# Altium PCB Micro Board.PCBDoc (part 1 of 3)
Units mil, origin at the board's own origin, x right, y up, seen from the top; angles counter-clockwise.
Board outline 8525 x 5525 mil, 2 copper layers (Top Layer, Bottom Layer); 82 components, 533 nets, 1257 pads, 165 vias.
Unrouted connection lines stored in the file: 4.
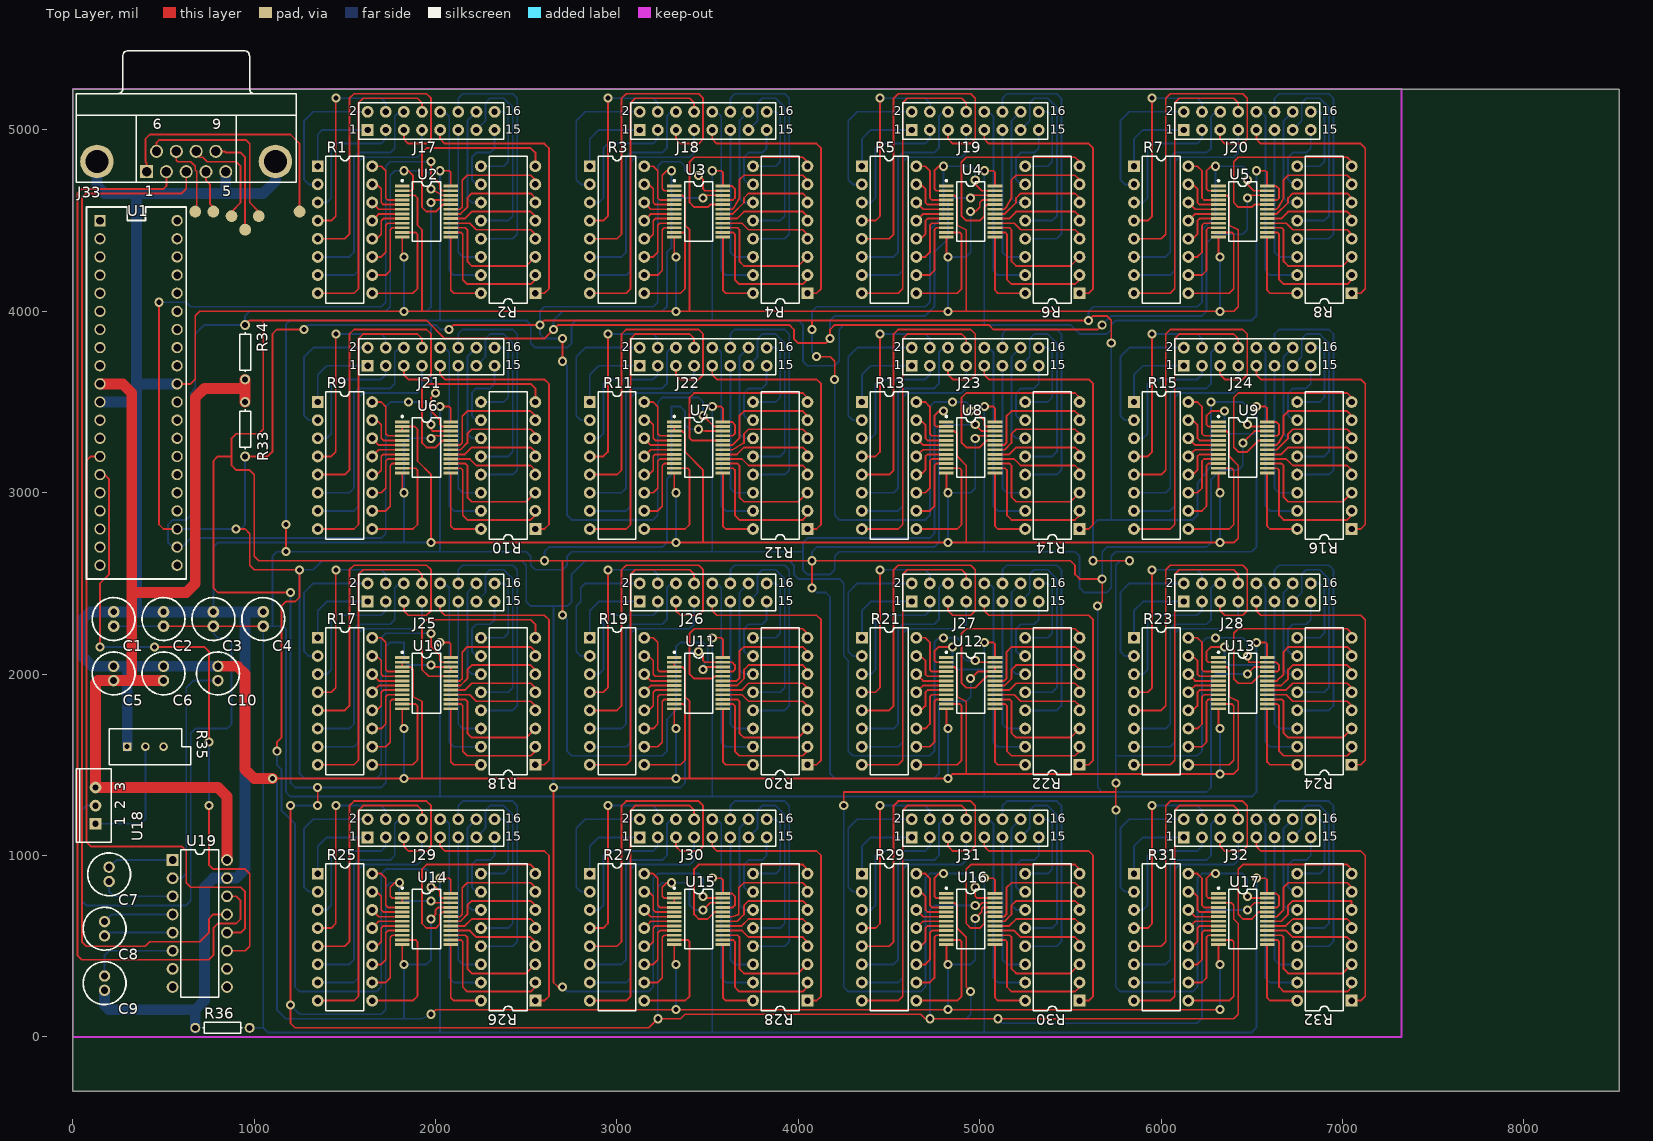
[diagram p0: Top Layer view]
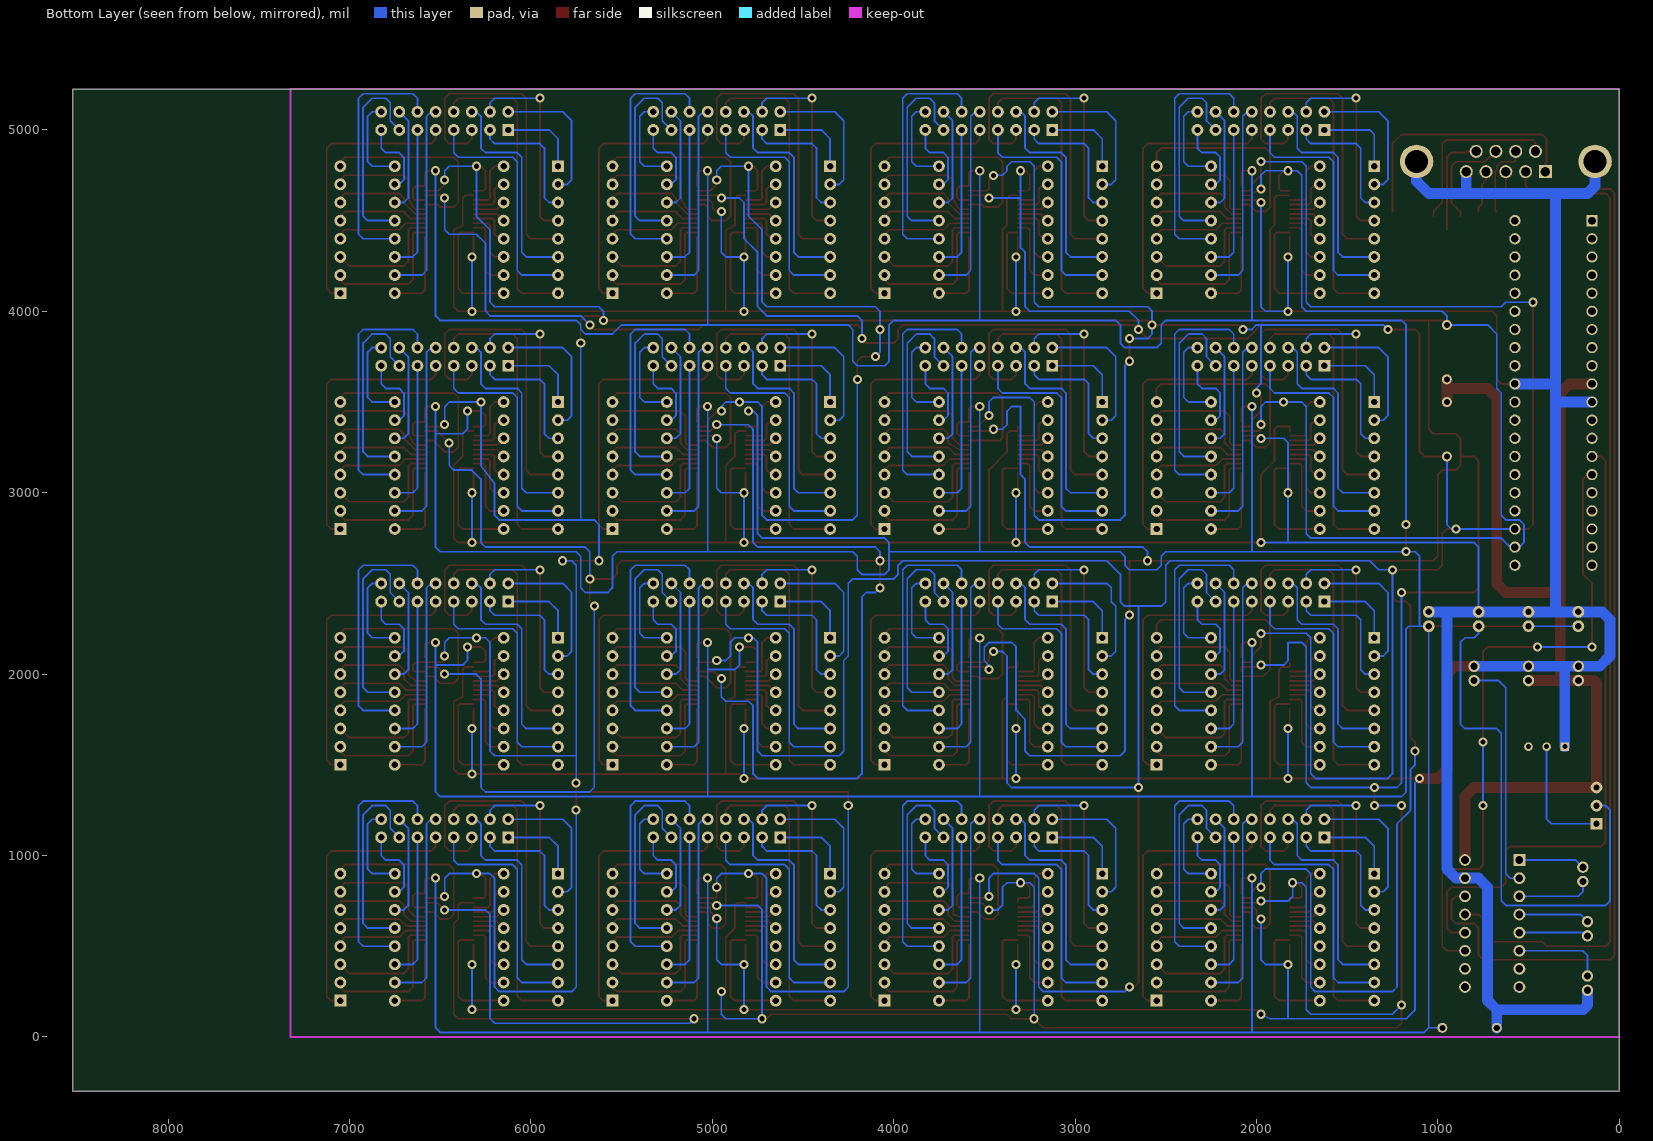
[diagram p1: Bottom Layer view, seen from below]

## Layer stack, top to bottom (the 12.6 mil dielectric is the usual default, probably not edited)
Top Layer: signal copper 1.4
Dielectric: dielectric 12.6, FR-4, Dk 4.8
Bottom Layer: signal copper 1.4

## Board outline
0,-300 8525,-300 8525,5225 0,5225

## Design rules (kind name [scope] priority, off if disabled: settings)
Clearance [All] p1: gap=9.84
ComponentClearance [All] p1: gap=10 collisioncheckmode=0
PolygonConnect [All] p1: connectstyle=Relief reliefconductorwidth=10 reliefentries=4 polygonreliefangle="90 Angle"
RoutingLayers [All] p1: top layer=Horizontal bottom layer=Vertical
RoutingVias [All] p1: holewidth=28 width=50 viastyle="Through Hole" minholewidth=28 minwidth=50 maxholewidth=28 maxwidth=50
SolderMaskExpansion [All] p1: expansion=4
TestPointUsage [All] p1: valid=0 allowmultiple=FALSE
Testpoint [All] p1: side=15 testpointundercomponent=TRUE minsize=40 maxsize=100 preferedsize=60 minholesize=0 maxholesize=40 preferedholesize=32 testpointgrid=1 style=1023 order=-539222988
Width [InNetClass('B[1..256]')] p1: maxlimit=10 minlimit=10 preferedwidth=10
16 further rules are at their usual default settings.

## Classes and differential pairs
component class "Drivers 1": C1 U2 U3 U4 U5
component class "Drivers 2": C2 U6 U7 U8 U9
component class "Drivers 3": C3 U10 U11 U12 U13
component class "Drivers 4": C4 U14 U15 U16 U17
component class Microprocessor: C5 C6 C7 C8 C9 C10 J33 R33 R34 R35 R36 U1 U18 U19
component class "Output Headers 1": J17 J18 J19 J20 J21 J22 J23 J24 J25 R1 R2 R3 R4 R5 R6 R7 R8 R9 R10 R11 R12 R13 R14 R15 R16 R17 R18
component class "Output Headers 2": J26 J27 J28 J29 J30 J31 J32 R19 R20 R21 R22 R23 R24 R25 R26 R27 R28 R29 R30 R31 R32
net class B[1..256]: B1 B2 B3 B4 B5 B6 B7 B8 B9 B10 B11 B12 B13 B14 B15 B16 B17 B18 B19 B20 B21 B22 B23 B24 B25 B26 B27 B28 B29 B30 B31 B32 B33 B34 B35 B36 B37 B38 B39 B40 B41 B42 B43 B44 B45 B46 B47 B48 B49 B50 B51 B52 B53 B54 B55 B56 B57 B58 B59 B60 B61 B62 B63 B64 B65 B66 B67 B68 B69 B70 B71 B72 B73 B74 B75 B76 B77 B78 B79 B80 B81 B82 B83 B84 B85 B86 B87 B88 B89 B90 B91 B92 B93 B94 B95 B96 B97 B98 B99 B100 B101 B102 B103 B104 B105 B106 B107 B108 B109 B110 B111 B112 B113 B114 B115 B116 B117 B118 B119 B120 B121 B122 B123 B124 B125 B126 B127 B128 B129 B130 B131 B132 B133 B134 B135 B136 B137 B138 B139 B140 B141 B142 B143 B144 B145 B146 B147 B148 B149 B150 B151 B152 B153 B154 B155 B156 B157 B158 B159 B160 B161 B162 B163 B164 B165 B166 B167 B168 B169 B170 B171 B172 B173 B174 B175 B176 B177 B178 B179 B180 B181 B182 B183 B184 B185 B186 B187 B188 B189 B190 B191 B192 B193 B194 B195 B196 B197 B198 B199 B200 B201 B202 B203 B204 B205 B206 B207 B208 B209 B210 B211 B212 B213 B214 B215 B216 B217 B218 B219 B220 B221 B222 B223 B224 B225 B226 B227 B228 B229 B230 B231 B232 B233 B234 B235 B236 B237 B238 B239 B240 B241 B242 B243 B244 B245 B246 B247 B248 B249 B250 B251 B252 B253 B254 B255 B256

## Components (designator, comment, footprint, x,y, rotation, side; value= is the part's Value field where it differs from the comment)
C1 "47nF" LED#1 225,2225 r0 top
C2 "47nF" LED#1 500,2225 r0 top
C3 "47nF" LED#1 775,2225 r0 top
C4 "47nF" LED#1 1050,2225 r0 top
C5 "0.1uF" LED#2 225,1925 r0 top
C6 "1uF" LED#2 500,1925 r0 top
C7 "1uF" LED#2 200,975 r180 top
C8 "1uF" LED#2 175,675 r180 top
C9 "1uF" LED#2 175,375 r180 top
C10 "1uF" LED#2 800,1925 r0 top
J17 "HDR2X8" HDR2X8 1625,5000 r0 top
J18 "HDR2X8" HDR2X8 3125,5000 r0 top
J19 "HDR2X8" HDR2X8 4625,5000 r0 top
J20 "HDR2X8" HDR2X8 6125,5000 r0 top
J21 "HDR2X8" HDR2X8 1625,3700 r0 top
J22 "HDR2X8" HDR2X8 3125,3700 r0 top
J23 "HDR2X8" HDR2X8 4625,3700 r0 top
J24 "HDR2X8" HDR2X8 6125,3700 r0 top
J25 "HDR2X8" HDR2X8 1625,2400 r0 top
J26 "HDR2X8" HDR2X8 3125,2400 r0 top
J27 "HDR2X8" HDR2X8 4625,2400 r0 top
J28 "HDR2X8" HDR2X8 6125,2400 r0 top
J29 "HDR2X8" HDR2X8 1625,1100 r0 top
J30 "HDR2X8" HDR2X8 3125,1100 r0 top
J31 "HDR2X8" HDR2X8 4625,1100 r0 top
J32 "HDR2X8" HDR2X8 6125,1100 r0 top
J33 "D Connector 9" DSUB1.385-2H9 625,5200 r0 top
R1 "330" DIP-16#1 1500,4450 r270 top
R2 "330" DIP-16#1 2400,4450 r90 top
R3 "330" DIP-16#1 3000,4450 r270 top
R4 "330" DIP-16#1 3900,4450 r90 top
R5 "330" DIP-16#1 4500,4450 r270 top
R6 "330" DIP-16#1 5400,4450 r90 top
R7 "330" DIP-16#1 6000,4450 r270 top
R8 "330" DIP-16#1 6900,4450 r90 top
R9 "330" DIP-16#1 1500,3150 r270 top
R10 "330" DIP-16#1 2400,3150 r90 top
R11 "330" DIP-16#1 3000,3150 r270 top
R12 "330" DIP-16#1 3900,3150 r90 top
R13 "330" DIP-16#1 4500,3150 r270 top
R14 "330" DIP-16#1 5400,3150 r90 top
R15 "330" DIP-16#1 6000,3150 r270 top
R16 "330" DIP-16#1 6900,3150 r90 top
R17 "330" DIP-16#1 1500,1850 r270 top
R18 "330" DIP-16#1 2400,1850 r90 top
R19 "330" DIP-16#1 3000,1850 r270 top
R20 "330" DIP-16#1 3900,1850 r90 top
R21 "330" DIP-16#1 4500,1850 r270 top
R22 "330" DIP-16#1 5400,1850 r90 top
R23 "330" DIP-16#1 6000,1850 r270 top
R24 "330" DIP-16#1 6900,1850 r90 top
R25 "330" DIP-16#1 1500,550 r270 top
R26 "330" DIP-16#1 2400,550 r90 top
R27 "330" DIP-16#1 3000,550 r270 top
R28 "330" DIP-16#1 3900,550 r90 top
R29 "330" DIP-16#1 4500,550 r270 top
R30 "330" DIP-16#1 5400,550 r90 top
R31 "330" DIP-16#1 6000,550 r270 top
R32 "330" DIP-16#1 6900,550 r90 top
R33 "1k8" AXIAL-0.3 950,3350 r90 top
R34 "1k8" AXIAL-0.3 950,3775 r270 top
R35 "1k" VR5 400,1600 r0 top
R36 "330" AXIAL-0.3 825,50 r0 top
U1 "ATMEGA16" DIP-40 75,2525 r0 top
U2 "MAX7313" SSO-G24/C6.8 1950,4550 r270 top
U3 "MAX7313" SSO-G24/C6.8 3450,4550 r270 top
U4 "MAX7313" SSO-G24/C6.8 4950,4550 r270 top
U5 "MAX7313" SSO-G24/C6.8 6450,4550 r270 top
U6 "MAX7313" SSO-G24/C6.8 1950,3250 r270 top
U7 "MAX7313" SSO-G24/C6.8 3450,3250 r270 top
U8 "MAX7313" SSO-G24/C6.8 4950,3250 r270 top
U9 "MAX7313" SSO-G24/C6.8 6450,3250 r270 top
U10 "MAX7313" SSO-G24/C6.8 1950,1950 r270 top
U11 "MAX7313" SSO-G24/C6.8 3450,1950 r270 top
U12 "MAX7313" SSO-G24/C6.8 4950,1950 r270 top
U13 "MAX7313" SSO-G24/C6.8 6450,1950 r270 top
U14 "MAX7313" SSO-G24/C6.8 1950,650 r270 top
U15 "MAX7313" SSO-G24/C6.8 3450,650 r270 top
U16 "MAX7313" SSO-G24/C6.8 4950,650 r270 top
U17 "MAX7313" SSO-G24/C6.8 6450,650 r270 top
U18 "LM317BT" SFM-T3/X1.6V 125,1275 r90 top
U19 "MAX232E" DIP-16#2 700,625 r270 top

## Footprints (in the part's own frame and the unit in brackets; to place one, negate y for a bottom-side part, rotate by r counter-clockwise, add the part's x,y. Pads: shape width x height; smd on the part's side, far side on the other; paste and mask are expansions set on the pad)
AXIAL-0.3 [mm]
  round 1.4 hole 0.85: 1(-3.81,0) 2(3.81,0)
  silkscreen extent -2.77,-0.76 2.77,0.76
DIP-16#1 [mil]
  rect 65x65 hole 35: 1(-350,-150)
  round 65 hole 35: 2(-250,-150) 3(-150,-150) 4(-50,-150) 5(50,-150) 6(150,-150) 7(250,-150) 8(350,-150) 9(350,150) 10(250,150) 11(150,150) 12(50,150) 13(-50,150) 14(-150,150) 15(-250,150) 16(-350,150)
  silkscreen extent -406,-104 406,104
DIP-16#2 [mil]
  rect 65x65 hole 42: 1(-350,-150)
  round 65 hole 42: 2(-250,-150) 3(-150,-150) 4(-50,-150) 5(50,-150) 6(150,-150) 7(250,-150) 8(350,-150) 9(350,150) 10(250,150) 11(150,150) 12(50,150) 13(-50,150) 14(-150,150) 15(-250,150) 16(-350,150)
  silkscreen extent -406,-104 406,104
DIP-40 [mil]
  rect 62x62 hole 42: 1(75,1975)
  round 62 hole 42: 2(75,1875) 3(75,1775) 4(75,1675) 5(75,1575) 6(75,1475) 7(75,1375) 8(75,1275) 9(75,1175) 10(75,1075) 11(75,975) 12(75,875) 13(75,775) 14(75,675) 15(75,575) 16(75,475) 17(75,375) 18(75,275) 19(75,175) 20(75,75) 21(500,75) 22(500,175) 23(500,275) 24(500,375) 25(500,475) 26(500,575) 27(500,675) 28(500,775) 29(500,875) 30(500,975) 31(500,1075) 32(500,1175) 33(500,1275) 34(500,1375) 35(500,1475) 36(500,1575) 37(500,1675) 38(500,1775) 39(500,1875) 40(500,1975)
  silkscreen extent 0,0 550,2050
DSUB1.385-2H9 [mil]
  rect 72x72 hole 52: 1(-218.11,-429.92)
  round 72 hole 52: 2(-109.06,-429.92) 3(0,-429.92) 4(109.06,-429.92) 5(218.11,-429.92) 6(-163.58,-318.11) 7(-54.53,-318.11) 8(54.53,-318.11) 9(163.58,-318.11)
  round 185 hole 125: 10(-491.93,-374.02) 11(491.93,-374.02)
  silkscreen extent -606,-488 606,236
HDR2X8 [mil]
  rect 65x65 hole 35: 1(0,0)
  round 65 hole 35: 2(0,100) 3(100,0) 4(100,100) 5(200,0) 6(200,100) 7(300,0) 8(300,100) 9(400,0) 10(400,100) 11(500,0) 12(500,100) 13(600,0) 14(600,100) 15(700,0) 16(700,100)
  silkscreen extent -50,-50 750,150
LED#1 [mil]
  round 65 hole 35: 1(0,39.37) 2(0,118.11)
  silkscreen extent -118,-39 118,197
LED#2 [mil]
  round 62.99 hole 39.37: 1(0,39.37) 2(0,118.11)
  silkscreen extent -118,-39 118,197
SFM-T3/X1.6V [mil]
  rect 65x65 hole 35: 1(-100,0)
  round 65 hole 35: 2(0,0) 3(100,0)
  silkscreen extent -203,-87 203,106
SSO-G24/C6.8 [mm]
  rect 0.4x2.05 smd: 1(-3.575,-3.4) 2(-2.925,-3.4) 3(-2.275,-3.4) 4(-1.625,-3.4) 5(-0.975,-3.4) 6(-0.325,-3.4) 7(0.325,-3.4) 8(0.975,-3.4) 9(1.625,-3.4) 10(2.275,-3.4) 11(2.925,-3.4) 12(3.575,-3.4) 13(3.575,3.4) 14(2.925,3.4) 15(2.275,3.4) 16(1.625,3.4) 17(0.975,3.4) 18(0.325,3.4) 19(-0.325,3.4) 20(-0.975,3.4) 21(-1.625,3.4) 22(-2.275,3.4) 23(-2.925,3.4) 24(-3.575,3.4)
  silkscreen extent -4.45,-3.52 4.18,1.98
VR5 [mm]
  rect 1.2x1.2 hole 0.7: 1(-2.54,0)
  round 1.2 hole 0.7: 2(0,0) 3(2.54,0)
  silkscreen extent -5.08,-2.54 6.35,2.54

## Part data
C1 C2 C3 C4 C5 C6 C7 C8 C9 C10: library part Cap, "Capacitor"
J17 J18 J19 J20 J21 J22 J23 J24 J25 J26 J27 J28 J29 J30 J31 J32: library part MHDR1X16, "Header, 16-Pin"
J33: "Receptacle Assembly, 9 Position, Right Angle"
R1 R2 R3 R4 R5 R6 R7 R8 R9 R10 R11 R12 R13 R14 R15 R16 R17 R18 R19 R20 R21 R22 R23 R24 R25 R26 R27 R28 R29 R30 R31 R32: library part "Res Pack2", "Resistor Array - Parts"
R33 R34 R36: library part Res1, "Resistor"
R35: library part RPot1, "Potentiometer"
U2 U3 U4 U5 U6 U7 U8 U9 U10 U11 U12 U13 U14 U15 U16 U17: library part "LED DRIVER"
U18: "3-Terminal Adjustable Positive Voltage Regulator"
U19: library part MAX232N, "Dual EIA-232 Driver/Receiver"

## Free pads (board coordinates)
  round 65 smd: 1(675,4550) 2(775,4550) 3(1250,4550) 4(875,4525) 5(950,4450) 6(1025,4525)

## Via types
v1: diameter 50, hole 28, Top Layer to Bottom Layer, 165 vias

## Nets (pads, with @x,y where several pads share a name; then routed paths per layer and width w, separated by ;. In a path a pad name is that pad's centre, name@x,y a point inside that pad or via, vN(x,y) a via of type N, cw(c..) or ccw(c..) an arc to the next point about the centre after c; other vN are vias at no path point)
+5: C5.1 C6.1 R33.2 R34.2 U1.10 U18.3 U19.16 | length 5664.5
  Top Layer w10: C5.1@214.37,1975 C5.1@225,1964.37
  Top Layer w60: U1.10@150,3600 275,3600 325,3550 325,1964.37 ; 325,2450 625,2450 675,2500 675,3525 725,3575 950,3575 ; C6.1@500,1964.37 139.37,1964.37 125,1950 U18.3@125,1375 800,1375 850,1325 U19.16@850,975 ; R33.2@950,3500 R34.2@950,3625
B1: R1.1 R1.16 U2.4 | length 331.1
  Top Layer w10: R1.16@1650,4800 1700,4800 1725,4775 1725,4625 1736.02,4613.98 U2.4@1816.14,4613.98
B1: J17.1 | length 460.4
  Bottom Layer w10: 1350,4800 1350,4950 1350,4975 1375,5000 J17.1@1625,5000
B2: R1.2 R1.15 U2.5 | length 256.3
  Top Layer w10: R1.15@1650,4700 1675,4700 1700,4675 1700,4600 1711.61,4588.39 U2.5@1816.14,4588.39
B2: J17.2 | length 781.1
  Bottom Layer w10: 1350,4700 1300,4700 1275,4725 1275,5050 1325,5100 J17.2@1625,5100
B3: R1.14 U2.6 | length 181.6
  Top Layer w10: R1.14@1650,4600 1687.2,4562.8 U2.6@1816.14,4562.8
B3: J17.3 R1.3 | length 731.1
  Bottom Layer w10: R1.3@1350,4600 1400,4600 1425,4625 1425,4900 1450,4925 1700,4925 1725,4950 J17.3@1725,5000
B4: R1.13 U2.7 | length 146.2
  Top Layer w10: 1675,4525 1687.2,4537.2 U2.7@1816.14,4537.2
B4: J17.4 R1.4 | length 1095.7
  Top Layer w10: R1.4@1350,4500 1425,4500 1450,4525 v1(1450,5175)
  Bottom Layer w10: v1(1450,5175) 1700,5175 1725,5150 J17.4@1725,5100
B5: R1.12 U2.8 | length 256.3
  Top Layer w10: R1.12@1650,4400 1675,4400 1700,4425 1700,4500 1711.61,4511.61 U2.8@1816.14,4511.61
B5: J17.5 R1.5 | length 1851.8
  Top Layer w10: R1.5@1350,4400 1500,4400 1525,4425 1525,5175 1550,5200 1950,5200 1975,5175 1975,4950 1950,4925 1850,4925 1825,4950 J17.5@1825,5000
B6: R1.11 U2.9 | length 331.1
  Top Layer w10: R1.11@1650,4300 1700,4300 1725,4325 1725,4475 1736.02,4486.02 U2.9@1816.14,4486.02
B6: J17.6 R1.6 | length 1216.4
  Bottom Layer w10: R1.6@1350,4300 1525,4300 1550,4325 1550,4850 1575,4875 1750,4875 1775,4900 1775,5075 1800,5100 J17.6@1825,5100
B7: R1.10 U2.10 | length 405.8
  Top Layer w10: R1.10@1650,4200 1725,4200 1750,4225 1750,4450 1760.43,4460.43 U2.10@1816.14,4460.43
B7: J17.7 R1.7 | length 1331.1
  Bottom Layer w10: R1.7@1350,4200 1550,4200 1575,4225 1575,4825 1600,4850 1900,4850 1925,4875 J17.7@1925,5000
B8: R1.9 U2.11 | length 648.3
  Top Layer w10: R1.9@1650,4100 1875,4100 1900,4125 1900,4425 1890.16,4434.84 U2.11@1816.14,4434.84
B8: J17.8 R1.8 | length 1681.1
  Top Layer w10: R1.8@1350,4100 1550,4100 1575,4125 1575,5150 1600,5175 1900,5175 1925,5150 J17.8@1925,5100
B9: R2.1 R2.16 U2.13 | length 465.9
  Top Layer w10: U2.13@2083.86,4409.25 2083.86,4116.14 2100,4100 R2.16@2250,4100
B9: J17.9 | length 1531.1
  Top Layer w10: J17.9@2025,5000 2025,4950 2050,4925 2600,4925 2625,4900 2625,4125 2600,4100 2550,4100
B10: J17.10 R2.15 | length 1095.7
  Bottom Layer w10: J17.10@2025,5100 2050,5100 2075,5075 2075,4225 2100,4200 R2.15@2250,4200
B10: R2.2 U2.14 | length 765.9
  Top Layer w10: U2.14@2083.86,4434.84 2140.16,4434.84 2150,4425 2150,4175 2175,4150 2525,4150 2550,4175 R2.2@2550,4200
B11: J17.11 R2.3 R2.14 | length 810.4
  Bottom Layer w10: J17.11@2125,5000 2125,4325 2150,4300 R2.14@2250,4300
B11: U2.15 | length 676.5
  Top Layer w10: U2.15@2083.86,4460.43 2164.57,4460.43 2175,4450 2175,4275 2200,4250 2500,4250 2550,4300
B12: J17.12 R2.13 | length 1381.1
  Bottom Layer w10: J17.12@2125,5100 2125,5175 2150,5200 2425,5200 2450,5175 2450,4425 2425,4400 R2.13@2250,4400
B12: R2.4 U2.16 | length 516.4
  Top Layer w10: U2.16@2083.86,4486.02 2188.98,4486.02 2225,4450 2525,4450 2550,4425 R2.4@2550,4400
B13: J17.13 R2.12 | length 1137.1
  Bottom Layer w10: J17.13@2225,5000 2275,5050 2275,5150 2300,5175 2375,5175 2425,5125 2425,4525 2400,4500 R2.12@2250,4500
B13: R2.5 U2.17 | length 517.4
  Top Layer w10: U2.17@2083.86,4511.61 2161.61,4511.61 2200,4550 2525,4550 2550,4525 R2.5@2550,4500
B14: J17.14 R2.11 | length 581.1
  Bottom Layer w10: J17.14@2225,5100 2175,5050 2175,4625 2200,4600 R2.11@2250,4600
B14: R2.6 U2.18 | length 577.5
  Top Layer w10: U2.18@2083.86,4537.2 2137.2,4537.2 2175,4575 2175,4625 2200,4650 2525,4650 2550,4625 R2.6@2550,4600
B15: J17.15 R2.10 | length 431.1
  Bottom Layer w10: R2.10@2250,4700 2225,4700 2200,4725 2200,4850 2225,4875 2300,4875 2325,4900 J17.15@2325,5000
B15: R2.7 U2.19 | length 665
  Top Layer w10: U2.19@2083.86,4562.8 2134.51,4562.8 2146.72,4575 2146.72,4721.72 2175,4750 2525,4750 2550,4725 R2.7@2550,4700
B16: J17.16 R2.9 | length 495.7
  Bottom Layer w10: R2.9@2250,4800 2375,4800 2400,4825 2400,5075 2375,5100 J17.16@2325,5100
B16: R2.8 U2.20 | length 1205.8
  Top Layer w10: U2.20@2083.86,4588.39 2038.39,4588.39 2000,4550 1950,4550 1925,4575 1925,4875 1950,4900 1975,4900 2525,4900 2550,4875 2550,4825 R2.8@2550,4800
B17: R3.16 U3.4 | length 331.1
  Top Layer w10: R3.16@3150,4800 3200,4800 3225,4775 3225,4625 3236.02,4613.98 U3.4@3316.14,4613.98
B17: J18.1 R3.1 | length 445.7
  Bottom Layer w10: R3.1@2850,4800 2850,4950 2900,5000 J18.1@3125,5000
B18: R3.15 U3.5 | length 256.3
  Top Layer w10: R3.15@3150,4700 3175,4700 3200,4675 3200,4600 3211.61,4588.39 U3.5@3316.14,4588.39
B18: J18.2 R3.2 | length 781.1
  Bottom Layer w10: R3.2@2850,4700 2800,4700 2775,4725 2775,5050 2825,5100 J18.2@3125,5100
B19: R3.14 U3.6 | length 181.6
  Top Layer w10: R3.14@3150,4600 3187.2,4562.8 U3.6@3316.14,4562.8
B19: J18.3 R3.3 | length 731.1
  Bottom Layer w10: R3.3@2850,4600 2900,4600 2925,4625 2925,4900 2950,4925 3200,4925 3225,4950 J18.3@3225,5000
B20: R3.13 U3.7 | length 146.2
  Top Layer w10: 3175,4525 3187.2,4537.2 U3.7@3316.14,4537.2
B20: J18.4 R3.4 | length 1095.7
  Top Layer w10: R3.4@2850,4500 2925,4500 2950,4525 v1(2950,5175)
  Bottom Layer w10: v1(2950,5175) 3200,5175 3225,5150 J18.4@3225,5100
B21: R3.12 U3.8 | length 256.3
  Top Layer w10: R3.12@3150,4400 3175,4400 3200,4425 3200,4500 3211.61,4511.61 U3.8@3316.14,4511.61
B21: J18.5 R3.5 | length 1851.8
  Top Layer w10: R3.5@2850,4400 3000,4400 3025,4425 3025,5175 3050,5200 3450,5200 3475,5175 3475,4950 3450,4925 3350,4925 3325,4950 J18.5@3325,5000
B22: R3.11 U3.9 | length 331.1
  Top Layer w10: R3.11@3150,4300 3200,4300 3225,4325 3225,4475 3236.02,4486.02 U3.9@3316.14,4486.02
B22: J18.6 R3.6 | length 1216.4
  Bottom Layer w10: R3.6@2850,4300 3025,4300 3050,4325 3050,4850 3075,4875 3250,4875 3275,4900 3275,5075 3300,5100 J18.6@3325,5100
B23: R3.10 U3.10 | length 405.8
  Top Layer w10: R3.10@3150,4200 3225,4200 3250,4225 3250,4450 3260.43,4460.43 U3.10@3316.14,4460.43
B23: J18.7 R3.7 | length 1331.1
  Bottom Layer w10: R3.7@2850,4200 3050,4200 3075,4225 3075,4825 3100,4850 3400,4850 3425,4875 J18.7@3425,5000
B24: R3.9 U3.11 | length 598.3
  Top Layer w10: R3.9@3150,4100 3350,4100 3375,4125 3375,4425 3365.16,4434.84 U3.11@3316.14,4434.84
B24: J18.8 R3.8 | length 1681.1
  Top Layer w10: R3.8@2850,4100 3050,4100 3075,4125 3075,5150 3100,5175 3400,5175 3425,5150 J18.8@3425,5100
B25: R4.16 U3.13 | length 465.9
  Top Layer w10: U3.13@3583.86,4409.25 3583.86,4116.14 3600,4100 R4.16@3750,4100
B25: J18.9 R4.1 | length 1531.1
  Top Layer w10: J18.9@3525,5000 3525,4950 3550,4925 4100,4925 4125,4900 4125,4125 4100,4100 R4.1@4050,4100
B26: J18.10 R4.15 | length 1095.7
  Bottom Layer w10: J18.10@3525,5100 3550,5100 3575,5075 3575,4225 3600,4200 R4.15@3750,4200
B26: R4.2 U3.14 | length 765.9
  Top Layer w10: U3.14@3583.86,4434.84 3640.16,4434.84 3650,4425 3650,4175 3675,4150 4025,4150 4050,4175 R4.2@4050,4200
B27: J18.11 R4.14 | length 810.4
  Bottom Layer w10: J18.11@3625,5000 3625,4325 3650,4300 R4.14@3750,4300
B27: R4.3 U3.15 | length 676.5
  Top Layer w10: U3.15@3583.86,4460.43 3664.57,4460.43 3675,4450 3675,4275 3700,4250 4000,4250 R4.3@4050,4300
B28: J18.12 R4.13 | length 1381.1
  Bottom Layer w10: J18.12@3625,5100 3625,5175 3650,5200 3925,5200 3950,5175 3950,4425 3925,4400 R4.13@3750,4400
B28: R4.4 U3.16 | length 516.4
  Top Layer w10: U3.16@3583.86,4486.02 3688.98,4486.02 3725,4450 4025,4450 4050,4425 R4.4@4050,4400
B29: J18.13 R4.12 | length 1137.1
  Bottom Layer w10: J18.13@3725,5000 3775,5050 3775,5150 3800,5175 3875,5175 3925,5125 3925,4525 3900,4500 R4.12@3750,4500
B29: R4.5 U3.17 | length 517.4
  Top Layer w10: U3.17@3583.86,4511.61 3661.61,4511.61 3700,4550 4025,4550 4050,4525 R4.5@4050,4500
B30: J18.14 R4.11 | length 581.1
  Bottom Layer w10: J18.14@3725,5100 3675,5050 3675,4625 3700,4600 R4.11@3750,4600
B30: R4.6 U3.18 | length 562.9
  Top Layer w10: U3.18@3583.86,4537.2 3637.2,4537.2 3700,4600 3700,4625 3725,4650 4025,4650 4050,4625 R4.6@4050,4600
B31: J18.15 R4.10 | length 431.1
  Bottom Layer w10: R4.10@3750,4700 3725,4700 3700,4725 3700,4850 3725,4875 3800,4875 3825,4900 J18.15@3825,5000
B31: R4.7 U3.19 | length 646.1
  Top Layer w10: U3.19@3583.86,4562.8 3634.51,4562.8 3646.72,4575 3675,4625 3675,4725 3700,4750 4025,4750 4050,4725 R4.7@4050,4700
B32: J18.16 R4.9 | length 495.7
  Bottom Layer w10: R4.9@3750,4800 3875,4800 3900,4825 3900,5075 3875,5100 J18.16@3825,5100
B32: R4.8 U3.20 | length 1120.5
  Top Layer w10: U3.20@3583.86,4588.39 3513.39,4588.39 3500,4575 3425,4575 3400,4600 3400,4825 3425,4850 4025,4850 4050,4825 R4.8@4050,4800
B33: R5.16 U4.4 | length 331.1
  Top Layer w10: R5.16@4650,4800 4700,4800 4725,4775 4725,4625 4736.02,4613.98 U4.4@4816.14,4613.98
B33: J19.1 R5.1 | length 445.7
  Bottom Layer w10: R5.1@4350,4800 4350,4950 4400,5000 J19.1@4625,5000
B34: R5.15 U4.5 | length 256.3
  Top Layer w10: R5.15@4650,4700 4675,4700 4700,4675 4700,4600 4711.61,4588.39 U4.5@4816.14,4588.39
B34: J19.2 R5.2 | length 781.1
  Bottom Layer w10: R5.2@4350,4700 4300,4700 4275,4725 4275,5050 4325,5100 J19.2@4625,5100
B35: R5.14 U4.6 | length 181.6
  Top Layer w10: R5.14@4650,4600 4687.2,4562.8 U4.6@4816.14,4562.8
B35: J19.3 R5.3 | length 731.1
  Bottom Layer w10: R5.3@4350,4600 4400,4600 4425,4625 4425,4900 4450,4925 4700,4925 4725,4950 J19.3@4725,5000
B36: R5.13 U4.7 | length 146.2
  Top Layer w10: 4675,4525 4687.2,4537.2 U4.7@4816.14,4537.2
B36: J19.4 R5.4 | length 1095.7
  Top Layer w10: R5.4@4350,4500 4425,4500 4450,4525 v1(4450,5175)
  Bottom Layer w10: v1(4450,5175) 4700,5175 4725,5150 J19.4@4725,5100
B37: R5.12 U4.8 | length 256.3
  Top Layer w10: R5.12@4650,4400 4675,4400 4700,4425 4700,4500 4711.61,4511.61 U4.8@4816.14,4511.61
B37: J19.5 R5.5 | length 1851.8
  Top Layer w10: R5.5@4350,4400 4500,4400 4525,4425 4525,5175 4550,5200 4950,5200 4975,5175 4975,4950 4950,4925 4850,4925 4825,4950 J19.5@4825,5000
B38: R5.11 U4.9 | length 331.1
  Top Layer w10: R5.11@4650,4300 4700,4300 4725,4325 4725,4475 4736.02,4486.02 U4.9@4816.14,4486.02
B38: J19.6 R5.6 | length 1216.4
  Bottom Layer w10: R5.6@4350,4300 4525,4300 4550,4325 4550,4850 4575,4875 4750,4875 4775,4900 4775,5075 4800,5100 J19.6@4825,5100
B39: R5.10 U4.10 | length 405.8
  Top Layer w10: R5.10@4650,4200 4725,4200 4750,4225 4750,4450 4760.43,4460.43 U4.10@4816.14,4460.43
B39: J19.7 R5.7 | length 1331.1
  Bottom Layer w10: R5.7@4350,4200 4550,4200 4575,4225 4575,4825 4600,4850 4900,4850 4925,4875 J19.7@4925,5000
B40: R5.9 U4.11 | length 648.3
  Top Layer w10: R5.9@4650,4100 4875,4100 4900,4125 4900,4425 4890.16,4434.84 U4.11@4816.14,4434.84
B40: J19.8 R5.8 | length 1681.1
  Top Layer w10: R5.8@4350,4100 4550,4100 4575,4125 4575,5150 4600,5175 4900,5175 4925,5150 J19.8@4925,5100
B41: J19.9 R6.1 | length 1531.1
  Top Layer w10: J19.9@5025,5000 5025,4950 5050,4925 5600,4925 5625,4900 5625,4125 5600,4100 R6.1@5550,4100
B41: R6.16 U4.13 | length 490.9
  Top Layer w10: U4.13@5083.86,4409.25 5083.86,4116.14 5100,4100 R6.16@5250,4100
  Bottom Layer w10: R6.16@5250,4075 R6.16@5250,4100
B42: J19.10 R6.15 | length 1095.7
  Bottom Layer w10: J19.10@5025,5100 5050,5100 5075,5075 5075,4225 5100,4200 R6.15@5250,4200
B42: R6.2 U4.14 | length 765.9
  Top Layer w10: U4.14@5083.86,4434.84 5140.16,4434.84 5150,4425 5150,4175 5175,4150 5525,4150 5550,4175 R6.2@5550,4200
B43: J19.11 R6.14 | length 810.4
  Bottom Layer w10: J19.11@5125,5000 5125,4325 5150,4300 R6.14@5250,4300
B43: R6.3 U4.15 | length 676.5
  Top Layer w10: U4.15@5083.86,4460.43 5164.57,4460.43 5175,4450 5175,4275 5200,4250 5500,4250 R6.3@5550,4300
B44: J19.12 R6.13 | length 1381.1
  Bottom Layer w10: J19.12@5125,5100 5125,5175 5150,5200 5425,5200 5450,5175 5450,4425 5425,4400 R6.13@5250,4400
B44: R6.4 U4.16 | length 516.4
  Top Layer w10: U4.16@5083.86,4486.02 5188.98,4486.02 5225,4450 5525,4450 5550,4425 R6.4@5550,4400
B45: J19.13 R6.12 | length 1137.1
  Bottom Layer w10: J19.13@5225,5000 5275,5050 5275,5150 5300,5175 5375,5175 5425,5125 5425,4525 5400,4500 R6.12@5250,4500
B45: R6.5 U4.17 | length 517.4
  Top Layer w10: U4.17@5083.86,4511.61 5161.61,4511.61 5200,4550 5525,4550 5550,4525 R6.5@5550,4500
B46: J19.14 R6.11 | length 581.1
  Bottom Layer w10: J19.14@5225,5100 5175,5050 5175,4625 5200,4600 R6.11@5250,4600
B46: R6.6 U4.18 | length 562.9
  Top Layer w10: U4.18@5083.86,4537.2 5137.2,4537.2 5200,4600 5200,4625 5225,4650 5525,4650 5550,4625 R6.6@5550,4600
B47: J19.15 R6.10 | length 431.1
  Bottom Layer w10: R6.10@5250,4700 5225,4700 5200,4725 5200,4850 5225,4875 5300,4875 5325,4900 J19.15@5325,5000
B47: R6.7 U4.19 | length 646.1
  Top Layer w10: U4.19@5083.86,4562.8 5134.51,4562.8 5146.72,4575 5175,4625 5175,4725 5200,4750 5525,4750 5550,4725 R6.7@5550,4700
B48: J19.16 R6.9 | length 495.7
  Bottom Layer w10: R6.9@5250,4800 5375,4800 5400,4825 5400,5075 5375,5100 J19.16@5325,5100
B48: R6.8 U4.20 | length 1255.8
  Top Layer w10: U4.20@5083.86,4588.39 5038.39,4588.39 5025,4575 5025,4525 5000,4500 4925,4500 4900,4525 4900,4825 4925,4850 5525,4850 5550,4825 R6.8@5550,4800
B49: R7.16 U5.4 | length 331.1
  Top Layer w10: R7.16@6150,4800 6200,4800 6225,4775 6225,4625 6236.02,4613.98 U5.4@6316.14,4613.98
B49: J20.1 R7.1 | length 445.7
  Bottom Layer w10: R7.1@5850,4800 5850,4950 5900,5000 J20.1@6125,5000
B50: R7.15 U5.5 | length 256.3
  Top Layer w10: R7.15@6150,4700 6175,4700 6200,4675 6200,4600 6211.61,4588.39 U5.5@6316.14,4588.39
B50: J20.2 R7.2 | length 781.1
  Bottom Layer w10: R7.2@5850,4700 5800,4700 5775,4725 5775,5050 5825,5100 J20.2@6125,5100
B51: R7.14 U5.6 | length 181.6
  Top Layer w10: R7.14@6150,4600 6187.2,4562.8 U5.6@6316.14,4562.8
B51: J20.3 R7.3 | length 731.1
  Bottom Layer w10: R7.3@5850,4600 5900,4600 5925,4625 5925,4900 5950,4925 6200,4925 6225,4950 J20.3@6225,5000
B52: R7.13 U5.7 | length 146.2
  Top Layer w10: 6175,4525 6187.2,4537.2 U5.7@6316.14,4537.2
B52: J20.4 R7.4 | length 1095.7
  Top Layer w10: R7.4@5850,4500 5925,4500 5950,4525 v1(5950,5175)
  Bottom Layer w10: v1(5950,5175) 6200,5175 6225,5150 J20.4@6225,5100
B53: R7.12 U5.8 | length 256.3
  Top Layer w10: R7.12@6150,4400 6175,4400 6200,4425 6200,4500 6211.61,4511.61 U5.8@6316.14,4511.61
B53: J20.5 R7.5 | length 1851.8
  Top Layer w10: R7.5@5850,4400 6000,4400 6025,4425 6025,5175 6050,5200 6450,5200 6475,5175 6475,4950 6450,4925 6350,4925 6325,4950 J20.5@6325,5000
B54: R7.11 U5.9 | length 331.1
  Top Layer w10: R7.11@6150,4300 6200,4300 6225,4325 6225,4475 6236.02,4486.02 U5.9@6316.14,4486.02
B54: J20.6 R7.6 | length 1216.4
  Bottom Layer w10: R7.6@5850,4300 6025,4300 6050,4325 6050,4850 6075,4875 6250,4875 6275,4900 6275,5075 6300,5100 J20.6@6325,5100
B55: R7.10 U5.10 | length 405.8
  Top Layer w10: R7.10@6150,4200 6225,4200 6250,4225 6250,4450 6260.43,4460.43 U5.10@6316.14,4460.43
B55: J20.7 R7.7 | length 1331.1
  Bottom Layer w10: R7.7@5850,4200 6050,4200 6075,4225 6075,4825 6100,4850 6400,4850 6425,4875 J20.7@6425,5000
B56: R7.9 U5.11 | length 648.3
  Top Layer w10: R7.9@6150,4100 6375,4100 6400,4125 6400,4425 6390.16,4434.84 U5.11@6316.14,4434.84
B56: J20.8 R7.8 | length 1681.1
  Top Layer w10: R7.8@5850,4100 6050,4100 6075,4125 6075,5150 6100,5175 6400,5175 6425,5150 J20.8@6425,5100
B57: R8.16 U5.13 | length 465.9
  Top Layer w10: U5.13@6583.86,4409.25 6583.86,4116.14 6600,4100 R8.16@6750,4100
B57: J20.9 R8.1 | length 1531.1
  Top Layer w10: J20.9@6525,5000 6525,4950 6550,4925 7100,4925 7125,4900 7125,4125 7100,4100 R8.1@7050,4100
B58: J20.10 R8.15 | length 1095.7
  Bottom Layer w10: J20.10@6525,5100 6550,5100 6575,5075 6575,4225 6600,4200 R8.15@6750,4200
B58: R8.2 U5.14 | length 765.9
  Top Layer w10: U5.14@6583.86,4434.84 6640.16,4434.84 6650,4425 6650,4175 6675,4150 7025,4150 7050,4175 R8.2@7050,4200
B59: J20.11 R8.14 | length 810.4
  Bottom Layer w10: J20.11@6625,5000 6625,4325 6650,4300 R8.14@6750,4300
B59: R8.3 U5.15 | length 676.5
  Top Layer w10: U5.15@6583.86,4460.43 6664.57,4460.43 6675,4450 6675,4275 6700,4250 7000,4250 R8.3@7050,4300
B60: J20.12 R8.13 | length 1381.1
  Bottom Layer w10: J20.12@6625,5100 6625,5175 6650,5200 6925,5200 6950,5175 6950,4425 6925,4400 R8.13@6750,4400
B60: R8.4 U5.16 | length 516.4
  Top Layer w10: U5.16@6583.86,4486.02 6688.98,4486.02 6725,4450 7025,4450 7050,4425 R8.4@7050,4400
B61: J20.13 R8.12 | length 1137.1
  Bottom Layer w10: J20.13@6725,5000 6775,5050 6775,5150 6800,5175 6875,5175 6925,5125 6925,4525 6900,4500 R8.12@6750,4500
B61: R8.5 U5.17 | length 517.4
  Top Layer w10: U5.17@6583.86,4511.61 6661.61,4511.61 6700,4550 7025,4550 7050,4525 R8.5@7050,4500
B62: J20.14 R8.11 | length 581.1
  Bottom Layer w10: J20.14@6725,5100 6675,5050 6675,4625 6700,4600 R8.11@6750,4600
B62: R8.6 U5.18 | length 562.9
  Top Layer w10: U5.18@6583.86,4537.2 6637.2,4537.2 6700,4600 6700,4625 6725,4650 7025,4650 7050,4625 R8.6@7050,4600
B63: J20.15 R8.10 | length 431.1
  Bottom Layer w10: R8.10@6750,4700 6725,4700 6700,4725 6700,4850 6725,4875 6800,4875 6825,4900 J20.15@6825,5000
B63: R8.7 U5.19 | length 646.1
  Top Layer w10: U5.19@6583.86,4562.8 6634.51,4562.8 6646.72,4575 6675,4625 6675,4725 6700,4750 7025,4750 7050,4725 R8.7@7050,4700
B64: J20.16 R8.9 | length 495.7
  Bottom Layer w10: R8.9@6750,4800 6875,4800 6900,4825 6900,5075 6875,5100 J20.16@6825,5100
B64: R8.8 U5.20 | length 1120.5
  Top Layer w10: U5.20@6583.86,4588.39 6513.39,4588.39 6500,4575 6425,4575 6400,4600 6400,4825 6425,4850 7025,4850 7050,4825 R8.8@7050,4800
B65: R9.16 U6.4 | length 331.1
  Top Layer w10: R9.16@1650,3500 1700,3500 1725,3475 1725,3325 1736.02,3313.98 U6.4@1816.14,3313.98
B65: J21.1 R9.1 | length 445.7
  Bottom Layer w10: R9.1@1350,3500 1350,3650 1400,3700 J21.1@1625,3700
B66: R9.15 U6.5 | length 256.3
  Top Layer w10: R9.15@1650,3400 1675,3400 1700,3375 1700,3300 1711.61,3288.39 U6.5@1816.14,3288.39
B66: J21.2 R9.2 | length 781.1
  Bottom Layer w10: R9.2@1350,3400 1300,3400 1275,3425 1275,3750 1325,3800 J21.2@1625,3800
B67: R9.14 U6.6 | length 181.6
  Top Layer w10: R9.14@1650,3300 1687.2,3262.8 U6.6@1816.14,3262.8
B67: J21.3 R9.3 | length 731.1
  Bottom Layer w10: R9.3@1350,3300 1400,3300 1425,3325 1425,3600 1450,3625 1700,3625 1725,3650 J21.3@1725,3700
B68: R9.13 U6.7 | length 146.2
  Top Layer w10: 1675,3225 1687.2,3237.2 U6.7@1816.14,3237.2
B68: J21.4 R9.4 | length 1095.7
  Top Layer w10: R9.4@1350,3200 1425,3200 1450,3225 v1(1450,3875)
  Bottom Layer w10: v1(1450,3875) 1700,3875 1725,3850 J21.4@1725,3800
B69: R9.12 U6.8 | length 256.3
  Top Layer w10: R9.12@1650,3100 1675,3100 1700,3125 1700,3200 1711.61,3211.61 U6.8@1816.14,3211.61
B69: J21.5 R9.5 | length 1851.8
  Top Layer w10: R9.5@1350,3100 1500,3100 1525,3125 1525,3875 1550,3900 1950,3900 1975,3875 1975,3650 1950,3625 1850,3625 1825,3650 J21.5@1825,3700
B70: R9.11 U6.9 | length 331.1
  Top Layer w10: R9.11@1650,3000 1700,3000 1725,3025 1725,3175 1736.02,3186.02 U6.9@1816.14,3186.02
B70: J21.6 R9.6 | length 1216.4
  Bottom Layer w10: R9.6@1350,3000 1525,3000 1550,3025 1550,3550 1575,3575 1750,3575 1775,3600 1775,3775 1800,3800 J21.6@1825,3800
B71: R9.10 U6.10 | length 405.8
  Top Layer w10: R9.10@1650,2900 1725,2900 1750,2925 1750,3150 1760.43,3160.43 U6.10@1816.14,3160.43
B71: J21.7 R9.7 | length 1331.1
  Bottom Layer w10: R9.7@1350,2900 1550,2900 1575,2925 1575,3525 1600,3550 1900,3550 1925,3575 J21.7@1925,3700
B72: R9.9 U6.11 | length 648.3
  Top Layer w10: R9.9@1650,2800 1875,2800 1900,2825 1900,3125 1890.16,3134.84 U6.11@1816.14,3134.84
B72: J21.8 R9.8 | length 1681.1
  Top Layer w10: R9.8@1350,2800 1550,2800 1575,2825 1575,3850 1600,3875 1900,3875 1925,3850 J21.8@1925,3800
B73: R10.16 U6.13 | length 465.9
  Top Layer w10: U6.13@2083.86,3109.25 2083.86,2816.14 2100,2800 R10.16@2250,2800
B73: J21.9 R10.1 | length 1531.1
  Top Layer w10: J21.9@2025,3700 2025,3650 2050,3625 2600,3625 2625,3600 2625,2825 2600,2800 R10.1@2550,2800
B74: J21.10 R10.15 | length 1095.7
  Bottom Layer w10: J21.10@2025,3800 2050,3800 2075,3775 2075,2925 2100,2900 R10.15@2250,2900
B74: R10.2 U6.14 | length 765.9
  Top Layer w10: U6.14@2083.86,3134.84 2140.16,3134.84 2150,3125 2150,2875 2175,2850 2525,2850 2550,2875 R10.2@2550,2900
B75: J21.11 R10.14 | length 810.4
  Bottom Layer w10: J21.11@2125,3700 2125,3025 2150,3000 R10.14@2250,3000
B75: R10.3 U6.15 | length 676.5
  Top Layer w10: U6.15@2083.86,3160.43 2164.57,3160.43 2175,3150 2175,2975 2200,2950 2500,2950 R10.3@2550,3000
B76: J21.12 R10.13 | length 1381.1
  Bottom Layer w10: J21.12@2125,3800 2125,3875 2150,3900 2425,3900 2450,3875 2450,3125 2425,3100 R10.13@2250,3100
B76: R10.4 U6.16 | length 516.4
  Top Layer w10: U6.16@2083.86,3186.02 2188.98,3186.02 2225,3150 2525,3150 2550,3125 R10.4@2550,3100
B77: J21.13 R10.12 | length 1137.1
  Bottom Layer w10: J21.13@2225,3700 2275,3750 2275,3850 2300,3875 2375,3875 2425,3825 2425,3225 2400,3200 R10.12@2250,3200
B77: R10.5 U6.17 | length 517.4
  Top Layer w10: U6.17@2083.86,3211.61 2161.61,3211.61 2200,3250 2525,3250 2550,3225 R10.5@2550,3200
B78: J21.14 R10.11 | length 581.1
  Bottom Layer w10: J21.14@2225,3800 2175,3750 2175,3325 2200,3300 R10.11@2250,3300
B78: R10.6 U6.18 | length 577.5
  Top Layer w10: U6.18@2083.86,3237.2 2137.2,3237.2 2175,3275 2175,3325 2200,3350 2525,3350 2550,3325 R10.6@2550,3300
B79: J21.15 R10.10 | length 431.1
  Bottom Layer w10: R10.10@2250,3400 2225,3400 2200,3425 2200,3550 2225,3575 2300,3575 2325,3600 J21.15@2325,3700
B79: R10.7 U6.19 | length 665
  Top Layer w10: U6.19@2083.86,3262.8 2134.51,3262.8 2146.72,3275 2146.72,3421.72 2175,3450 2525,3450 2550,3425 R10.7@2550,3400
B80: J21.16 R10.9 | length 495.7
  Bottom Layer w10: R10.9@2250,3500 2375,3500 2400,3525 2400,3775 2375,3800 J21.16@2325,3800
B80: R10.8 U6.20 | length 1205.8
  Top Layer w10: U6.20@2083.86,3288.39 2038.39,3288.39 2000,3250 1950,3250 1925,3275 1925,3575 1950,3600 2525,3600 2550,3575 2550,3525 R10.8@2550,3500
B81: R11.16 U7.4 | length 331.1
  Top Layer w10: R11.16@3150,3500 3200,3500 3225,3475 3225,3325 3236.02,3313.98 U7.4@3316.14,3313.98
B81: J22.1 R11.1 | length 445.7
  Bottom Layer w10: R11.1@2850,3500 2850,3650 2900,3700 J22.1@3125,3700
B82: R11.15 U7.5 | length 256.3
  Top Layer w10: R11.15@3150,3400 3175,3400 3200,3375 3200,3300 3211.61,3288.39 U7.5@3316.14,3288.39
B82: J22.2 R11.2 | length 781.1
  Bottom Layer w10: R11.2@2850,3400 2800,3400 2775,3425 2775,3750 2825,3800 J22.2@3125,3800
B83: R11.14 U7.6 | length 181.6
  Top Layer w10: R11.14@3150,3300 3187.2,3262.8 U7.6@3316.14,3262.8
B83: J22.3 R11.3 | length 731.1
  Bottom Layer w10: R11.3@2850,3300 2900,3300 2925,3325 2925,3600 2950,3625 3200,3625 3225,3650 J22.3@3225,3700
B84: R11.13 U7.7 | length 146.2
  Top Layer w10: 3175,3225 3187.2,3237.2 U7.7@3316.14,3237.2
B84: J22.4 R11.4 | length 1095.7
  Top Layer w10: R11.4@2850,3200 2925,3200 2950,3225 v1(2950,3875)
  Bottom Layer w10: v1(2950,3875) 3200,3875 3225,3850 J22.4@3225,3800
B85: R11.12 U7.8 | length 256.3
  Top Layer w10: R11.12@3150,3100 3175,3100 3200,3125 3200,3200 3211.61,3211.61 U7.8@3316.14,3211.61
B85: J22.5 R11.5 | length 1851.8
  Top Layer w10: R11.5@2850,3100 3000,3100 3025,3125 3025,3875 3050,3900 3450,3900 3475,3875 3475,3650 3450,3625 3350,3625 3325,3650 J22.5@3325,3700
B86: R11.11 U7.9 | length 331.1
  Top Layer w10: R11.11@3150,3000 3200,3000 3225,3025 3225,3175 3236.02,3186.02 U7.9@3316.14,3186.02
B86: J22.6 R11.6 | length 1216.4
  Bottom Layer w10: R11.6@2850,3000 3025,3000 3050,3025 3050,3550 3075,3575 3250,3575 3275,3600 3275,3775 3300,3800 J22.6@3325,3800
B87: R11.10 U7.10 | length 405.8
  Top Layer w10: R11.10@3150,2900 3225,2900 3250,2925 3250,3150 3260.43,3160.43 U7.10@3316.14,3160.43
B87: J22.7 R11.7 | length 1331.1
  Bottom Layer w10: R11.7@2850,2900 3050,2900 3075,2925 3075,3525 3100,3550 3400,3550 3425,3575 J22.7@3425,3700
B88: R11.9 U7.11 | length 648.3
  Top Layer w10: R11.9@3150,2800 3375,2800 3400,2825 3400,3125 3390.16,3134.84 U7.11@3316.14,3134.84
B88: J22.8 R11.8 | length 1681.1
  Top Layer w10: R11.8@2850,2800 3050,2800 3075,2825 3075,3850 3100,3875 3400,3875 3425,3850 J22.8@3425,3800
B89: R12.16 U7.13 | length 465.9
  Top Layer w10: U7.13@3583.86,3109.25 3583.86,2816.14 3600,2800 R12.16@3750,2800
B89: J22.9 R12.1 | length 1531.1
  Top Layer w10: J22.9@3525,3700 3525,3650 3550,3625 4100,3625 4125,3600 4125,2825 4100,2800 R12.1@4050,2800
B90: J22.10 R12.15 | length 1095.7
  Bottom Layer w10: J22.10@3525,3800 3550,3800 3575,3775 3575,2925 3600,2900 R12.15@3750,2900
